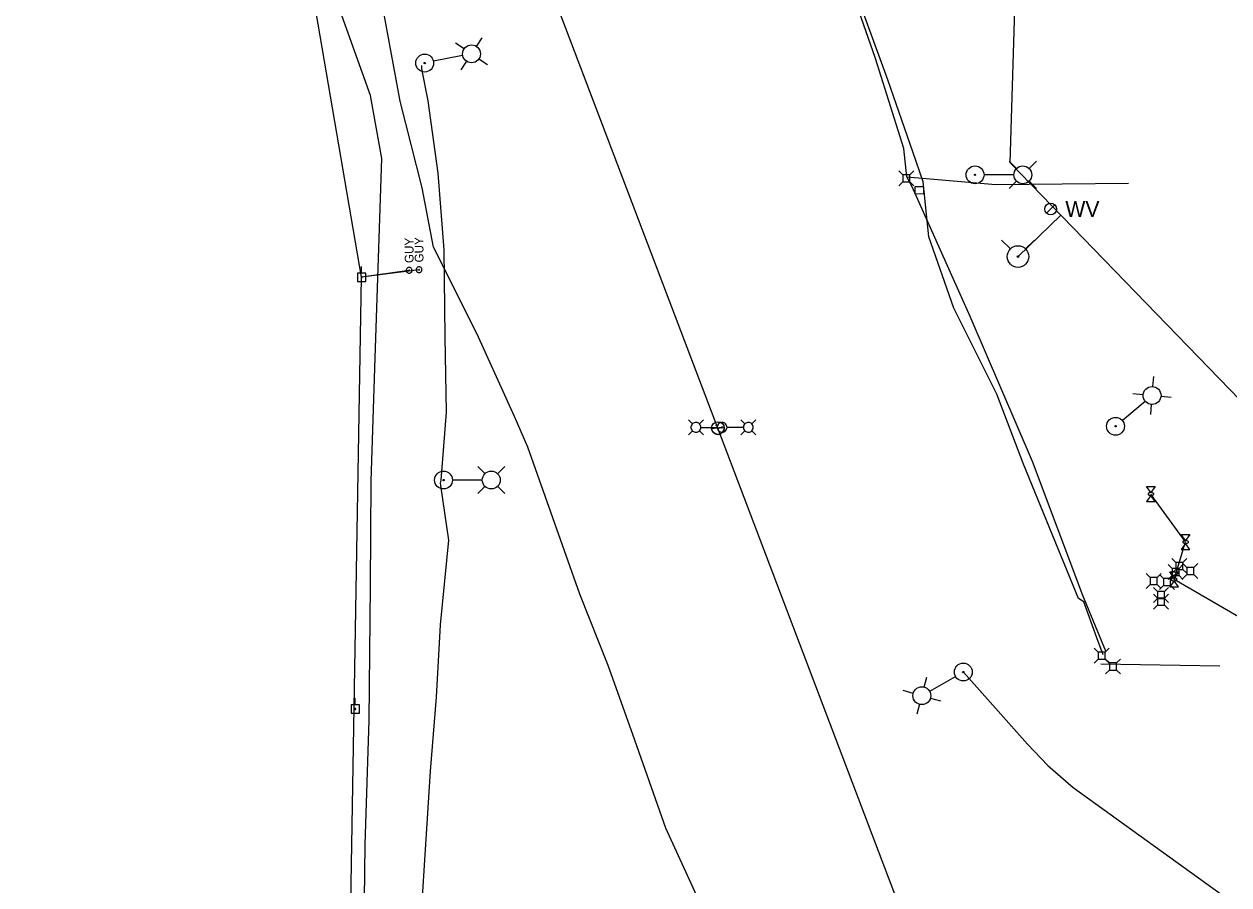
# Model space of a CAD drawing. Extents: x 596028 to 606371, y 330010 to 403088.
# Drawn here: x 603307 to 603840, y 350562 to 350943 of the extents above; entities that cross this region are included whole.
import ezdxf

# ---------------------------------------------------------------- set-up
doc = ezdxf.new("R2010")
doc.units = 0
for name, color, linetype in [('E_FTMS_Conduit', 7, 'Continuous'), ('E_LTG', 7, 'Continuous'), ('E_LTG_CID', 7, 'Continuous'), ('E_UTL_E', 7, 'Continuous'), ('E_UTL_E_Bold', 7, 'Continuous'), ('E_UTL_E_UG', 7, 'Continuous'), ('E_UTL_EGuyWire', 7, 'Continuous'), ('E_UTL_EPowerPole', 7, 'Continuous'), ('E_UTL_FO_UG_QWEST', 7, 'Continuous'), ('E_UTL_Overhead', 7, 'Continuous'), ('E_UTL_T', 7, 'Continuous'), ('E_UTL_T_UG', 7, 'Continuous'), ('E_UTL_TV', 7, 'Continuous'), ('E_UTL_W', 7, 'Continuous'), ('E_UTL_W_UG', 7, 'Continuous'), ('E_UTL_WHydrant', 7, 'Continuous')]:
    doc.layers.add(name, color=color, linetype=linetype)

# ---------------------------------------------------------------- blocks, each defined once
blk = doc.blocks.new('_U272')
at = {"layer": 'E_LTG'}
blk.add_lwpolyline([(0.001, -0.171), (0.001, 0.172)], dxfattribs=at)
blk.add_circle((0.001, 0), 0.171, dxfattribs=at)
blk.add_arc((0.001, 0), 0.171, 90, 270, dxfattribs=at)
blk.add_text('L', height=0.108, dxfattribs=at).set_placement((0.066, -0.042))

msp = doc.modelspace()

# ---------------------------------------------------------------- linework, layer by layer
at = {"layer": 'E_FTMS_Conduit'}
msp.add_lwpolyline([(603609.26, 350547.29), (603590.93, 350587.57), (603576.33, 350628.92), (603565.39, 350659.37), (603552.92, 350690.81), (603529.87, 350755.72), (603524.01, 350769.33), (603507.4, 350805.93), (603488.24, 350844.06), (603483.2, 350870.26), (603473.58, 350908.61), (603465.8, 350950.07), (603458.47, 350983.69), (603437.61, 351034.41), (603419.58, 351080.05), (603403.21, 351158.05), (603376.31, 351235.86), (603345.63, 351318.27), (603314.78, 351397.25), (603283.64, 351476.72)], dxfattribs=at)
at = {"layer": 'E_LTG'}
for points in [[(603501.8, 350931.66), (603498.01, 350934.2)], [(603507.24, 350932.72), (603509.79, 350936.51)], [(603501.1, 350928.7), (603488.3, 350926.19)], [(603502.87, 350926.22), (603500.32, 350922.43)], [(603508.3, 350927.29), (603512.09, 350924.73)], [(603745.82, 350878.83), (603742.59, 350882.05)], [(603751.36, 350878.83), (603754.59, 350882.05)], [(603744.57, 350876.05), (603731.52, 350876.05)], [(603745.82, 350873.29), (603742.59, 350870.05)], [(603751.36, 350873.29), (603754.59, 350870.05)], [(603806.02, 350782.51), (603806.41, 350787.06)], [(603801.79, 350778.94), (603797.23, 350779.32)], [(603802.61, 350776.01), (603792.63, 350767.6)], [(603805.36, 350774.7), (603804.97, 350770.15)], [(603809.59, 350778.27), (603814.14, 350777.88)], [(603602.64, 350766.07), (603600.87, 350767.84)], [(603602.64, 350763.02), (603600.87, 350761.24)], [(603606.34, 350764.54), (603606.31, 350764.96), (603606.19, 350765.35), (603606, 350765.72), (603605.74, 350766.05), (603605.43, 350766.32), (603605.07, 350766.52), (603604.68, 350766.66), (603604.27, 350766.72), (603603.86, 350766.7), (603603.46, 350766.6), (603603.08, 350766.43), (603602.74, 350766.19), (603602.46, 350765.89), (603602.24, 350765.54), (603602.08, 350765.16), (603602, 350764.75), (603602, 350764.34), (603602.08, 350763.93), (603602.24, 350763.55), (603602.46, 350763.2), (603602.74, 350762.9), (603603.08, 350762.66), (603603.46, 350762.49), (603603.86, 350762.39), (603604.27, 350762.37), (603604.68, 350762.43), (603605.07, 350762.56), (603605.43, 350762.77), (603605.74, 350763.04), (603606, 350763.37), (603606.19, 350763.74), (603606.31, 350764.13), (603606.34, 350764.54)], [(603605.69, 350766.07), (603607.47, 350767.84)], [(603605.69, 350763.02), (603607.47, 350761.24)], [(603606.38, 350764.54), (603613.56, 350764.54)], [(603617.91, 350764.54), (603617.87, 350764.96), (603617.75, 350765.35), (603617.56, 350765.72), (603617.31, 350766.04), (603617, 350766.32), (603616.64, 350766.52), (603616.25, 350766.66), (603615.84, 350766.72), (603615.43, 350766.7), (603615.02, 350766.6), (603614.65, 350766.43), (603614.31, 350766.19), (603614.02, 350765.89), (603613.8, 350765.54), (603613.65, 350765.16), (603613.57, 350764.75), (603613.57, 350764.34), (603613.65, 350763.93), (603613.8, 350763.55), (603614.02, 350763.2), (603614.31, 350762.9), (603614.65, 350762.66), (603615.02, 350762.49), (603615.43, 350762.39), (603615.84, 350762.37), (603616.25, 350762.43), (603616.64, 350762.56), (603617, 350762.77), (603617.31, 350763.04), (603617.56, 350763.37), (603617.75, 350763.73), (603617.87, 350764.13), (603617.91, 350764.54)], [(603615.9, 350764.54), (603615.9, 350764.57), (603615.89, 350764.61), (603615.87, 350764.63), (603615.86, 350764.66), (603615.83, 350764.68), (603615.8, 350764.69), (603615.77, 350764.71), (603615.74, 350764.71), (603615.71, 350764.71), (603615.68, 350764.7), (603615.65, 350764.69), (603615.63, 350764.67), (603615.6, 350764.65), (603615.59, 350764.62), (603615.58, 350764.59), (603615.57, 350764.56), (603615.57, 350764.53), (603615.58, 350764.5), (603615.59, 350764.47), (603615.6, 350764.44), (603615.63, 350764.42), (603615.65, 350764.4), (603615.68, 350764.39), (603615.71, 350764.38), (603615.74, 350764.38), (603615.77, 350764.38), (603615.8, 350764.39), (603615.83, 350764.41), (603615.86, 350764.43), (603615.87, 350764.45), (603615.89, 350764.48), (603615.9, 350764.51), (603615.9, 350764.54)], [(603625.13, 350764.54), (603617.95, 350764.54)], [(603625.82, 350766.07), (603624.04, 350767.84)], [(603625.82, 350763.02), (603624.04, 350761.24)], [(603629.51, 350764.54), (603629.47, 350764.96), (603629.36, 350765.35), (603629.17, 350765.72), (603628.91, 350766.04), (603628.6, 350766.32), (603628.24, 350766.52), (603627.85, 350766.66), (603627.44, 350766.72), (603627.03, 350766.7), (603626.63, 350766.6), (603626.25, 350766.43), (603625.91, 350766.19), (603625.63, 350765.89), (603625.4, 350765.54), (603625.25, 350765.16), (603625.17, 350764.75), (603625.17, 350764.34), (603625.25, 350763.93), (603625.4, 350763.55), (603625.63, 350763.2), (603625.91, 350762.9), (603626.25, 350762.66), (603626.63, 350762.49), (603627.03, 350762.39), (603627.44, 350762.37), (603627.85, 350762.43), (603628.24, 350762.56), (603628.6, 350762.77), (603628.91, 350763.04), (603629.17, 350763.37), (603629.36, 350763.73), (603629.47, 350764.13), (603629.51, 350764.54)], [(603628.86, 350766.07), (603630.64, 350767.84)], [(603628.86, 350763.02), (603630.64, 350761.24)], [(603511, 350744.06), (603507.77, 350747.28)], [(603516.54, 350744.06), (603519.77, 350747.28)], [(603509.74, 350741.28), (603496.69, 350741.28)], [(603511, 350738.51), (603507.77, 350735.28)], [(603516.54, 350738.51), (603519.77, 350735.28)], [(603705.02, 350649.81), (603706.22, 350654.22)], [(603707.48, 350648.03), (603718.82, 350654.5)], [(603700.21, 350647.06), (603695.8, 350648.27)], [(603702.95, 350642.25), (603701.75, 350637.85)], [(603707.77, 350645), (603712.17, 350643.8)]]:
    msp.add_lwpolyline(points, dxfattribs=at)
for centre, radius in [((603505.05, 350929.47), 3.96), ((603484.35, 350925.41), 3.96), ((603484.35, 350925.41), 0.303), ((603727.49, 350876.05), 3.96), ((603748.59, 350876.05), 3.96), ((603727.49, 350876.05), 0.303), ((603805.69, 350778.6), 3.96), ((603789.56, 350765), 3.96), ((603789.56, 350765), 0.303), ((603492.67, 350741.28), 3.96), ((603492.67, 350741.28), 0.303), ((603513.77, 350741.28), 3.96), ((603722.31, 350656.49), 3.96), ((603722.31, 350656.49), 0.303), ((603703.99, 350646.04), 3.96)]:
    msp.add_circle(centre, radius, dxfattribs=at)
at = {"layer": 'E_LTG_CID'}
for points in [[(604318.05, 348339.7), (604287.36, 348606.91), (604242.16, 348872.6), (604188.57, 349120.13), (604125.01, 349362.84), (604050.82, 349602.08), (604014.23, 349708.06), (603966.43, 349837.54), (603869.82, 350091.09), (603838.85, 350172.22), (603784.41, 350315.72), (603699.29, 350539.43), (603613.87, 350764.2), (603510.34, 351036.54), (603442.84, 351213.06), (603357.76, 351436.96)], [(603483.27, 350554.85), (603484.6, 350575.79), (603486.87, 350612.75), (603489.62, 350645.46), (603491.33, 350677.37), (603495.09, 350714.78), (603491.49, 350738.84), (603491.38, 350740.03), (603491.57, 350741.16), (603494.03, 350771.18), (603493.35, 350804.53), (603492.94, 350842.91), (603490.29, 350876.8), (603485.83, 350908.69), (603483.11, 350922.88), (603483.11, 350924.33)], [(603613.87, 350764.2), (603615.73, 350764.54)], [(603722.32, 350656.5), (603750.61, 350624.59), (603759.58, 350615.18), (603770.81, 350605.51), (603836.23, 350558.44)]]:
    msp.add_lwpolyline(points, dxfattribs=at)
at = {"layer": 'E_UTL_E'}
for points in [[(603816.14, 350704.93), (603814.39, 350706.68)], [(603819.24, 350704.93), (603816.14, 350704.93)], [(603816.14, 350704.93), (603816.14, 350701.83)], [(603819.24, 350704.93), (603820.99, 350706.68)], [(603819.24, 350701.83), (603819.24, 350704.93)], [(603821.03, 350702.59), (603819.27, 350704.35)], [(603824.12, 350702.59), (603825.87, 350704.35)], [(603810.76, 350697.74), (603809.01, 350699.49)], [(603814.51, 350702.19), (603812.75, 350703.94)], [(603814.51, 350699.09), (603812.75, 350697.34)], [(603813.86, 350697.74), (603815.61, 350699.49)], [(603816.14, 350701.83), (603814.39, 350700.08)], [(603817.6, 350702.19), (603814.51, 350702.19)], [(603814.51, 350702.19), (603814.51, 350699.09)], [(603814.51, 350699.09), (603817.6, 350699.09)], [(603816.14, 350701.83), (603819.24, 350701.83)], [(603817.6, 350702.19), (603819.35, 350703.94)], [(603817.6, 350699.09), (603817.6, 350702.19)], [(603817.6, 350699.09), (603819.35, 350697.34)], [(603819.24, 350701.83), (603820.99, 350700.08)], [(603821.03, 350699.5), (603819.27, 350697.75)], [(603824.12, 350702.59), (603821.03, 350702.59)], [(603821.03, 350702.59), (603821.03, 350699.5)], [(603821.03, 350699.5), (603824.12, 350699.5)], [(603824.12, 350699.5), (603824.12, 350702.59)], [(603824.12, 350699.5), (603825.87, 350697.75)], [(603808.06, 350692.04), (603806.31, 350693.79)], [(603810.76, 350694.65), (603809.01, 350692.89)], [(603813.86, 350697.74), (603810.76, 350697.74)], [(603810.76, 350697.74), (603810.76, 350694.65)], [(603810.76, 350694.65), (603813.86, 350694.65)], [(603811.16, 350692.04), (603812.91, 350693.79)], [(603813.86, 350694.65), (603813.86, 350697.74)], [(603813.86, 350694.65), (603815.61, 350692.89)], [(603808.06, 350688.94), (603806.31, 350687.19)], [(603808.1, 350689.16), (603806.35, 350690.91)], [(603811.16, 350692.04), (603808.06, 350692.04)], [(603808.06, 350692.04), (603808.06, 350688.94)], [(603808.06, 350688.94), (603811.16, 350688.94)], [(603811.2, 350689.16), (603808.1, 350689.16)], [(603808.1, 350689.16), (603808.1, 350686.06)], [(603811.16, 350688.94), (603811.16, 350692.04)], [(603811.16, 350688.94), (603812.91, 350687.19)], [(603811.2, 350689.16), (603812.95, 350690.91)], [(603811.2, 350686.06), (603811.2, 350689.16)], [(603808.1, 350686.06), (603806.35, 350684.31)], [(603808.1, 350686.06), (603811.2, 350686.06)], [(603811.2, 350686.06), (603812.95, 350684.31)]]:
    msp.add_lwpolyline(points, dxfattribs=at)
at = {"layer": 'E_UTL_E_Bold'}
for points in [[(603803.29, 350738.38), (603807.1, 350738.38)], [(603805.19, 350735.72), (603803.29, 350738.38)], [(603807.1, 350738.38), (603805.19, 350735.72)], [(603805.19, 350734.45), (603803.29, 350731.78)], [(603803.29, 350731.78), (603807.1, 350731.78)], [(603806.46, 350735.08), (603806.44, 350735.2), (603806.37, 350735.32), (603806.26, 350735.42), (603806.11, 350735.52), (603805.93, 350735.6), (603805.72, 350735.66), (603805.49, 350735.7), (603805.25, 350735.72), (603805.01, 350735.71), (603804.78, 350735.68), (603804.56, 350735.63), (603804.36, 350735.56), (603804.19, 350735.47), (603804.06, 350735.37), (603803.97, 350735.26), (603803.93, 350735.14), (603803.93, 350735.02), (603803.97, 350734.9), (603804.06, 350734.79), (603804.19, 350734.69), (603804.36, 350734.6), (603804.56, 350734.53), (603804.78, 350734.48), (603805.01, 350734.45), (603805.25, 350734.45), (603805.49, 350734.46), (603805.72, 350734.5), (603805.93, 350734.56), (603806.11, 350734.64), (603806.26, 350734.74), (603806.37, 350734.84), (603806.44, 350734.96), (603806.46, 350735.08)], [(603807.1, 350731.78), (603805.19, 350734.45)], [(603818.62, 350717.22), (603822.43, 350717.22)], [(603820.52, 350714.55), (603818.62, 350717.22)], [(603822.43, 350717.22), (603820.52, 350714.55)], [(603820.52, 350713.28), (603818.62, 350710.62)], [(603818.62, 350710.62), (603822.43, 350710.62)], [(603821.79, 350713.92), (603821.77, 350714.04), (603821.7, 350714.15), (603821.59, 350714.26), (603821.44, 350714.35), (603821.26, 350714.43), (603821.05, 350714.49), (603820.82, 350714.53), (603820.58, 350714.55), (603820.34, 350714.54), (603820.11, 350714.52), (603819.89, 350714.47), (603819.69, 350714.39), (603819.52, 350714.31), (603819.39, 350714.21), (603819.3, 350714.09), (603819.26, 350713.98), (603819.26, 350713.85), (603819.3, 350713.74), (603819.39, 350713.62), (603819.52, 350713.52), (603819.69, 350713.44), (603819.89, 350713.36), (603820.11, 350713.31), (603820.34, 350713.29), (603820.58, 350713.28), (603820.82, 350713.3), (603821.05, 350713.34), (603821.26, 350713.4), (603821.44, 350713.48), (603821.59, 350713.57), (603821.7, 350713.68), (603821.77, 350713.79), (603821.79, 350713.92)], [(603822.43, 350710.62), (603820.52, 350713.28)], [(603813.53, 350700.67), (603817.34, 350700.67)], [(603815.44, 350698.01), (603813.53, 350700.67)], [(603817.34, 350700.67), (603815.44, 350698.01)], [(603815.44, 350696.74), (603813.53, 350694.07)], [(603813.53, 350694.07), (603817.34, 350694.07)], [(603816.71, 350697.37), (603816.68, 350697.49), (603816.62, 350697.61), (603816.51, 350697.72), (603816.36, 350697.81), (603816.17, 350697.89), (603815.96, 350697.95), (603815.74, 350697.99), (603815.5, 350698.01), (603815.26, 350698), (603815.02, 350697.97), (603814.8, 350697.92), (603814.61, 350697.85), (603814.44, 350697.76), (603814.31, 350697.66), (603814.22, 350697.55), (603814.17, 350697.43), (603814.17, 350697.31), (603814.22, 350697.19), (603814.31, 350697.08), (603814.44, 350696.98), (603814.61, 350696.89), (603814.8, 350696.82), (603815.02, 350696.77), (603815.26, 350696.74), (603815.5, 350696.74), (603815.74, 350696.75), (603815.96, 350696.79), (603816.17, 350696.85), (603816.36, 350696.93), (603816.51, 350697.03), (603816.62, 350697.14), (603816.68, 350697.25), (603816.71, 350697.37)], [(603817.34, 350694.07), (603815.44, 350696.74)]]:
    msp.add_lwpolyline(points, dxfattribs=at)
at = {"layer": 'E_UTL_E_UG'}
msp.add_lwpolyline([(603859.63, 350671.8), (603815.44, 350697.37), (603820.52, 350713.92), (603805.19, 350735.08)], dxfattribs=at)
at = {"layer": 'E_UTL_EGuyWire'}
for p in [(603481.87, 350834.14), (603477.49, 350833.87)]:
    msp.add_line(p, (603456.5, 350830.83), dxfattribs=at)
for points in [[(603477.49, 350835.15), (603477.25, 350835.13), (603477.01, 350835.06), (603476.79, 350834.95), (603476.6, 350834.8), (603476.44, 350834.61), (603476.32, 350834.4), (603476.24, 350834.17), (603476.21, 350833.93), (603476.22, 350833.69), (603476.28, 350833.45), (603476.38, 350833.23), (603476.52, 350833.03), (603476.69, 350832.86), (603476.9, 350832.73), (603477.13, 350832.64), (603477.37, 350832.59), (603477.61, 350832.59), (603477.85, 350832.64), (603478.08, 350832.73), (603478.28, 350832.86), (603478.46, 350833.03), (603478.6, 350833.23), (603478.7, 350833.45), (603478.76, 350833.69), (603478.77, 350833.93), (603478.74, 350834.17), (603478.66, 350834.4), (603478.53, 350834.61), (603478.37, 350834.8), (603478.18, 350834.95), (603477.96, 350835.06), (603477.73, 350835.13), (603477.49, 350835.15)], [(603477.49, 350834.03), (603477.46, 350834.03), (603477.43, 350834.02), (603477.4, 350834), (603477.38, 350833.99), (603477.36, 350833.96), (603477.34, 350833.94), (603477.33, 350833.91), (603477.33, 350833.88), (603477.33, 350833.85), (603477.34, 350833.82), (603477.35, 350833.79), (603477.37, 350833.76), (603477.39, 350833.74), (603477.41, 350833.73), (603477.44, 350833.72), (603477.47, 350833.71), (603477.5, 350833.71), (603477.53, 350833.72), (603477.56, 350833.73), (603477.59, 350833.74), (603477.61, 350833.76), (603477.63, 350833.79), (603477.64, 350833.82), (603477.65, 350833.85), (603477.65, 350833.88), (603477.64, 350833.91), (603477.63, 350833.94), (603477.62, 350833.96), (603477.6, 350833.99), (603477.57, 350834), (603477.55, 350834.02), (603477.52, 350834.03), (603477.49, 350834.03)], [(603481.87, 350835.42), (603481.63, 350835.4), (603481.39, 350835.33), (603481.18, 350835.22), (603480.99, 350835.07), (603480.83, 350834.88), (603480.7, 350834.67), (603480.62, 350834.44), (603480.59, 350834.2), (603480.6, 350833.95), (603480.66, 350833.72), (603480.76, 350833.5), (603480.9, 350833.3), (603481.08, 350833.13), (603481.28, 350833), (603481.51, 350832.91), (603481.75, 350832.86), (603481.99, 350832.86), (603482.23, 350832.91), (603482.46, 350833), (603482.66, 350833.13), (603482.84, 350833.3), (603482.98, 350833.5), (603483.08, 350833.72), (603483.14, 350833.95), (603483.15, 350834.2), (603483.12, 350834.44), (603483.04, 350834.67), (603482.92, 350834.88), (603482.76, 350835.07), (603482.56, 350835.22), (603482.35, 350835.33), (603482.11, 350835.4), (603481.87, 350835.42)], [(603481.87, 350834.3), (603481.84, 350834.29), (603481.81, 350834.29), (603481.78, 350834.27), (603481.76, 350834.25), (603481.74, 350834.23), (603481.73, 350834.2), (603481.72, 350834.17), (603481.71, 350834.14), (603481.71, 350834.11), (603481.72, 350834.08), (603481.73, 350834.06), (603481.75, 350834.03), (603481.77, 350834.01), (603481.8, 350833.99), (603481.83, 350833.98), (603481.86, 350833.98), (603481.89, 350833.98), (603481.92, 350833.98), (603481.94, 350833.99), (603481.97, 350834.01), (603481.99, 350834.03), (603482.01, 350834.06), (603482.02, 350834.08), (603482.03, 350834.11), (603482.03, 350834.14), (603482.03, 350834.17), (603482.02, 350834.2), (603482, 350834.23), (603481.98, 350834.25), (603481.96, 350834.27), (603481.93, 350834.29), (603481.9, 350834.29), (603481.87, 350834.3)]]:
    msp.add_lwpolyline(points, dxfattribs=at)
at = {"layer": 'E_UTL_EPowerPole'}
for points in [[(603458.31, 350832.68), (603454.63, 350832.68)], [(603454.63, 350832.68), (603454.63, 350828.98)], [(603456.47, 350832.68), (603456.47, 350835.58)], [(603458.31, 350828.98), (603458.31, 350832.68)], [(603454.63, 350828.98), (603458.31, 350828.98)], [(603456.74, 350830.83), (603456.74, 350830.88), (603456.72, 350830.92), (603456.7, 350830.96), (603456.68, 350831), (603456.64, 350831.03), (603456.6, 350831.05), (603456.56, 350831.06), (603456.51, 350831.07), (603456.47, 350831.07), (603456.43, 350831.06), (603456.38, 350831.04), (603456.35, 350831.01), (603456.32, 350830.98), (603456.29, 350830.94), (603456.27, 350830.9), (603456.27, 350830.86), (603456.27, 350830.81), (603456.27, 350830.77), (603456.29, 350830.72), (603456.32, 350830.69), (603456.35, 350830.65), (603456.38, 350830.63), (603456.43, 350830.61), (603456.47, 350830.6), (603456.51, 350830.59), (603456.56, 350830.6), (603456.6, 350830.62), (603456.64, 350830.64), (603456.68, 350830.67), (603456.7, 350830.7), (603456.72, 350830.74), (603456.74, 350830.79), (603456.74, 350830.83)], [(603455.48, 350642.06), (603451.8, 350642.06)], [(603451.8, 350642.06), (603451.8, 350638.37)], [(603453.91, 350640.22), (603453.91, 350640.27), (603453.89, 350640.31), (603453.87, 350640.35), (603453.85, 350640.38), (603453.81, 350640.41), (603453.77, 350640.44), (603453.73, 350640.45), (603453.68, 350640.46), (603453.64, 350640.46), (603453.6, 350640.45), (603453.55, 350640.43), (603453.52, 350640.4), (603453.49, 350640.37), (603453.46, 350640.33), (603453.44, 350640.29), (603453.44, 350640.24), (603453.44, 350640.2), (603453.44, 350640.15), (603453.46, 350640.11), (603453.49, 350640.07), (603453.52, 350640.04), (603453.55, 350640.01), (603453.6, 350639.99), (603453.64, 350639.98), (603453.68, 350639.98), (603453.73, 350639.99), (603453.77, 350640), (603453.81, 350640.03), (603453.85, 350640.06), (603453.87, 350640.09), (603453.89, 350640.13), (603453.91, 350640.17), (603453.91, 350640.22)], [(603453.64, 350642.06), (603453.64, 350644.97)], [(603455.48, 350638.37), (603455.48, 350642.06)], [(603451.8, 350638.37), (603455.48, 350638.37)]]:
    msp.add_lwpolyline(points, dxfattribs=at)
at = {"layer": 'E_UTL_FO_UG_QWEST'}
msp.add_lwpolyline([(603457.26, 350519.89), (603458.06, 350580.31), (603459.78, 350635.27), (603460.41, 350694.56), (603460.42, 350694.52), (603460.77, 350740.82), (603462.52, 350795.19), (603465.43, 350883.25), (603460.42, 350911.12), (603422.96, 351015.55), (603399.52, 351073.87), (603379.61, 351132.32), (603357.48, 351186), (603338.12, 351234.94), (603318.47, 351290.15), (603261.54, 351443.61)], dxfattribs=at)
at = {"layer": 'E_UTL_Overhead'}
msp.add_lwpolyline([(603468.46, 350246.59), (603449.86, 350441.98), (603456.5, 350830.83), (603431.88, 350974.54), (603298.9, 351326.49)], dxfattribs=at)
at = {"layer": 'E_UTL_T'}
for points in [[(603695.56, 350876.08), (603693.81, 350877.84)], [(603698.66, 350876.08), (603695.56, 350876.08)], [(603695.56, 350876.08), (603695.56, 350872.99)], [(603698.66, 350876.08), (603700.41, 350877.84)], [(603698.66, 350872.99), (603698.66, 350876.08)], [(603695.56, 350872.99), (603693.81, 350871.24)], [(603695.56, 350872.99), (603698.66, 350872.99)], [(603698.66, 350872.99), (603700.41, 350871.24)], [(603781.94, 350665.22), (603780.19, 350666.97)], [(603785.04, 350665.22), (603786.79, 350666.97)], [(603781.94, 350662.12), (603780.19, 350660.37)], [(603785.04, 350665.22), (603781.94, 350665.22)], [(603781.94, 350665.22), (603781.94, 350662.12)], [(603781.94, 350662.12), (603785.04, 350662.12)], [(603785.04, 350662.12), (603785.04, 350665.22)], [(603785.04, 350662.12), (603786.79, 350660.37)], [(603786.88, 350660.48), (603785.13, 350662.23)], [(603789.98, 350660.48), (603791.73, 350662.23)], [(603786.88, 350657.38), (603785.13, 350655.63)], [(603789.98, 350660.48), (603786.88, 350660.48)], [(603786.88, 350660.48), (603786.88, 350657.38)], [(603786.88, 350657.38), (603789.98, 350657.38)], [(603789.98, 350657.38), (603789.98, 350660.48)], [(603789.98, 350657.38), (603791.73, 350655.63)]]:
    msp.add_lwpolyline(points, dxfattribs=at)
msp.add_lwpolyline([(603700.85, 350867.76), (603704.85, 350867.72), (603704.88, 350870.72), (603700.88, 350870.76)], close=True, dxfattribs=at)
at = {"layer": 'E_UTL_T_UG'}
msp.add_line((603783.02, 350660.08), (603835.68, 350659.25), dxfattribs=at)
for points in [[(603697.35, 350875.17), (603695.97, 350887.71), (603683.55, 350927.48), (603666.68, 350975.49), (603643.57, 351021.93), (603626.19, 351071.29), (603577.12, 351199.32), (603609.14, 351233.94)], [(603704.58, 350873.02), (603699.95, 350886.22), (603688.96, 350917.97), (603670.36, 350968.89), (603654.5, 351013.15), (603635.58, 351061.48), (603619.18, 351111.24), (603602.55, 351154.33), (603585.57, 351197.86), (603601.34, 351220.63), (603623.32, 351223.76), (603638.74, 351226.02), (603705.22, 351228.11)], [(603697.35, 350875.17), (603736.7, 350871.77), (603795.36, 350872.41)], [(603785.24, 350665.74), (603775.09, 350690.35), (603752.83, 350749.44), (603725.4, 350813.49), (603699.65, 350870.72), (603697.35, 350875.17)], [(603784.12, 350664.03), (603781.27, 350671.61), (603775.51, 350687.51), (603773.27, 350688.93), (603748.96, 350748.31), (603737.15, 350779.15), (603718.12, 350817.17), (603707.06, 350848.74), (603704.58, 350873.02)]]:
    msp.add_lwpolyline(points, dxfattribs=at)
at = {"layer": 'E_UTL_TV'}
for points in [[(603804.84, 350698.26), (603803.09, 350700.01)], [(603807.94, 350698.26), (603809.69, 350700.01)], [(603804.84, 350695.17), (603803.09, 350693.41)], [(603807.94, 350698.26), (603804.84, 350698.26)], [(603804.84, 350698.26), (603804.84, 350695.17)], [(603804.84, 350695.17), (603807.94, 350695.17)], [(603807.94, 350695.17), (603807.94, 350698.26)], [(603807.94, 350695.17), (603809.69, 350693.41)]]:
    msp.add_lwpolyline(points, dxfattribs=at)
at = {"layer": 'E_UTL_W'}
msp.add_lwpolyline([(603759.08, 350859.13), (603762.75, 350862.8)], dxfattribs=at)
msp.add_circle((603760.91, 350860.96), 2.59, dxfattribs=at)
at = {"layer": 'E_UTL_W_UG'}
msp.add_line((603765.38, 350858.28), (603746.48, 350839.96), dxfattribs=at)
msp.add_lwpolyline([(603848.58, 350733.11), (603849.18, 350771.81), (603743.07, 350881.3), (603749.01, 351080.21), (603844.81, 351171.86), (604184.2, 351164.46)], dxfattribs=at)
at = {"layer": 'E_UTL_WHydrant'}
for points in [[(603743.15, 350843.3), (603739.25, 350847.19)], [(603749.82, 350843.3), (603753.71, 350847.19)]]:
    msp.add_lwpolyline(points, dxfattribs=at)
for radius in [4.77, 0.365]:
    msp.add_circle((603746.48, 350839.96), radius, dxfattribs=at)

# ---------------------------------------------------------------- block references
at = {"layer": 'E_LTG_CID', "xscale": 16.404166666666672, "yscale": 16.404166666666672, "rotation": 97.82095686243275}
msp.add_blockref('_U272', (603613.88, 350764.19), dxfattribs=at)

# ---------------------------------------------------------------- texts
at = {"layer": 'E_UTL_EGuyWire'}
for p in [(603479.41, 350837.08), (603483.8, 350837.35)]:
    msp.add_text('GUY', height=3.85, rotation=90, dxfattribs=at).set_placement(p)
at = {"layer": 'E_UTL_W'}
msp.add_text('WV', height=7, dxfattribs=at).set_placement((603767.39, 350857.46))

doc.saveas('drawing.dxf')
